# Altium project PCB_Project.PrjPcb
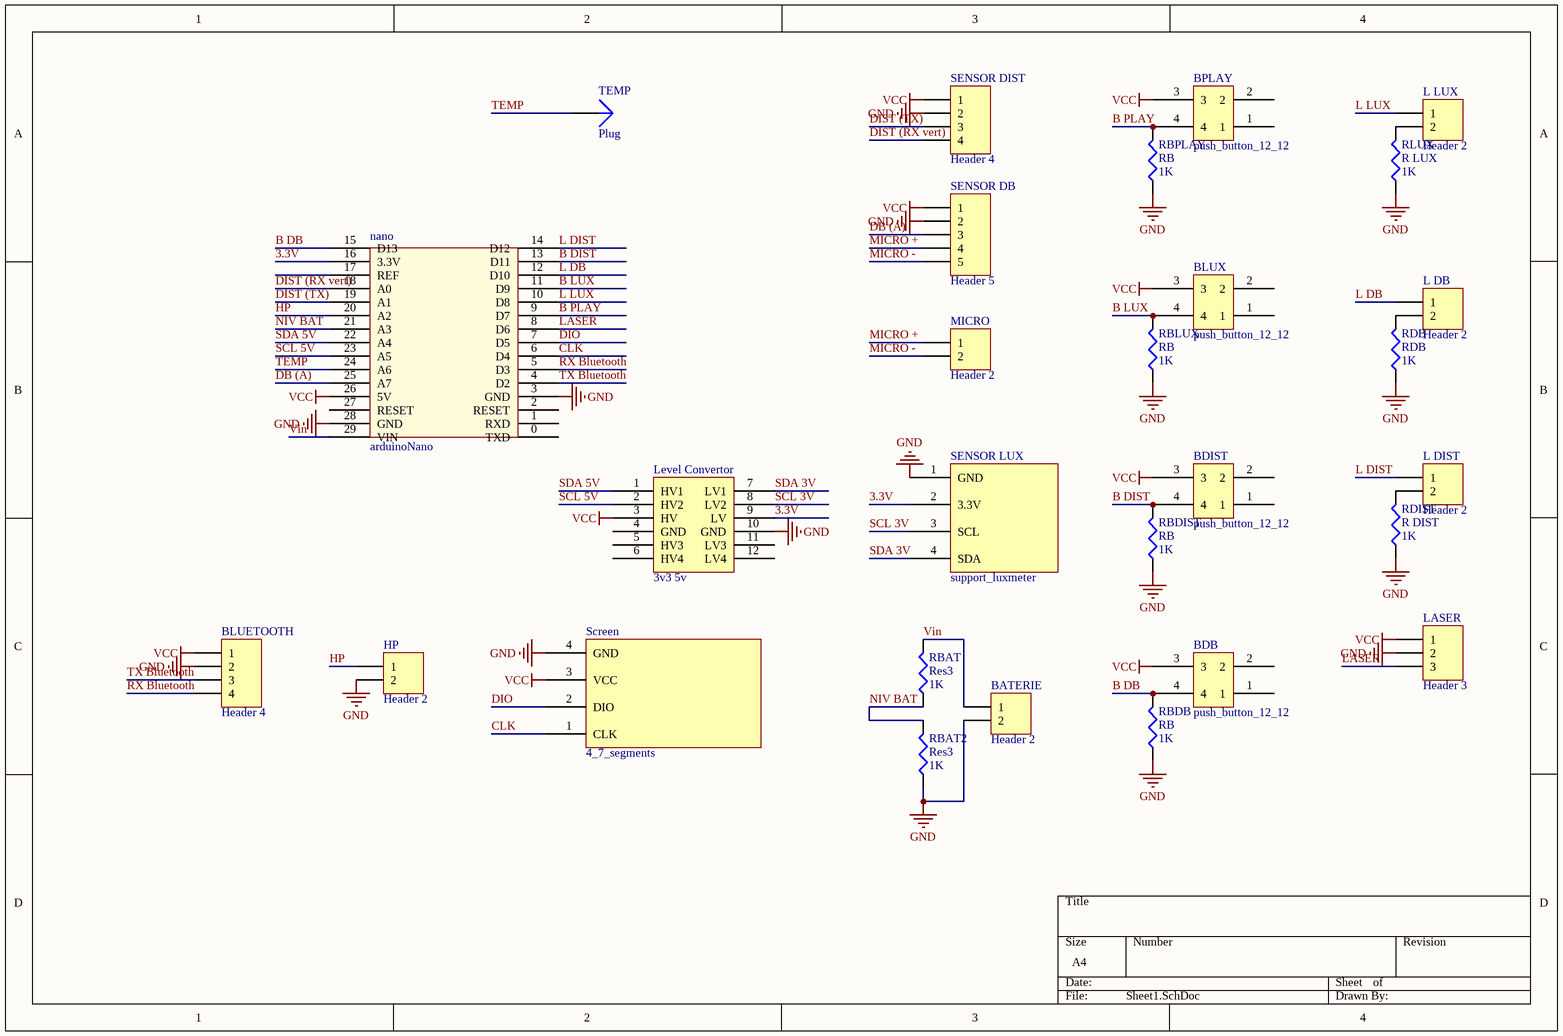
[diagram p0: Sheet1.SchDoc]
1 sheet, 28 parts. Net scope: global (net labels, ports and power ports of the same name join across sheets).
Board file: PCB1.PcbDoc

## Sheet Sheet1.SchDoc
size A4

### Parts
BATERIE  Header 2  [HDR1X2]
BDB  push_button_12_12  [push_button_12_12]
BDIST  push_button_12_12  [push_button_12_12]
BLUETOOTH  Header 4  [HDR1X4]
BLUX  push_button_12_12  [push_button_12_12]
BPLAY  push_button_12_12  [push_button_12_12]
HP  Header 2  [HDR1X2]
L_DB  Header 2  [HDR1X2]
L_DIST  Header 2  [HDR1X2]
L_LUX  Header 2  [HDR1X2]
LASER  Header 3  [HDR1X3]
Level_Convertor  3v3 5v  [level_convertor]
MICRO  Header 2  [HDR1X2]
nano  arduinoNano  [Arduino nano]
RBAT  Res3  value 1K  [C1206]
RBAT2  Res3  value 1K  [C1206]
RBDB  RB  value 1K  [C1206]
RBDIST  RB  value 1K  [C1206]
RBLUX  RB  value 1K  [C1206]
RBPLAY  RB  value 1K  [C1206]
RDB  RDB  value 1K  [C1206]
RDIST  R DIST  value 1K  [C1206]
RLUX  R LUX  value 1K  [C1206]
Screen  4_7_segments  [4_7_segment]
SENSOR_DB  Header 5  [HDR1X5]
SENSOR_DIST  Header 4  [HDR1X4]
SENSOR_LUX  support_luxmeter  [support_luxmeter]
TEMP  Plug  [PIN1]

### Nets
GND: BATERIE.2 BLUETOOTH.2 HP.2 LASER.2 Level_Convertor.10(GND) nano.3(GND) nano.28(GND) RBAT2.1 RBDB.1 RBDIST.1 RBLUX.1 RBPLAY.1 RDB.1 RDIST.1 RLUX.1 Screen.4(GND) SENSOR_DB.2 SENSOR_DIST.2 SENSOR_LUX.1(GND)
VCC: BDB.3 BDIST.3 BLUETOOTH.1 BLUX.3 BPLAY.3 LASER.1 Level_Convertor.3(HV) nano.26(5V) Screen.3(VCC) SENSOR_DB.1 SENSOR_DIST.1
3.3V: Level_Convertor.9(LV) nano.16(3.3V) SENSOR_LUX.2(3.3V)
B DB: BDB.4 nano.15(D13) RBDB.2
B DIST: BDIST.4 nano.13(D11) RBDIST.2
B LUX: BLUX.4 nano.11(D9) RBLUX.2
B PLAY: BPLAY.4 nano.9(D7) RBPLAY.2
CLK: nano.6(D4) Screen.1(CLK)
DB (A): nano.25(A7) SENSOR_DB.3
DIO: nano.7(D5) Screen.2(DIO)
DIST (RX vert): nano.18(A0) SENSOR_DIST.4
DIST (TX): nano.19(A1) SENSOR_DIST.3
HP: HP.1 nano.20(A2)
L DB: L_DB.1 nano.12(D10)
L DIST: L_DIST.1 nano.14(D12)
L LUX: L_LUX.1 nano.10(D8)
LASER: LASER.3 nano.8(D6)
MICRO +: MICRO.1 SENSOR_DB.4
MICRO -: MICRO.2 SENSOR_DB.5
NIV BAT: nano.21(A3) RBAT.1 RBAT2.2
RX Bluetooth: BLUETOOTH.4 nano.5(D3)
SCL 3V: Level_Convertor.8(LV2) SENSOR_LUX.3(SCL)
SCL 5V: Level_Convertor.2(HV2) nano.23(A5)
SDA 3V: Level_Convertor.7(LV1) SENSOR_LUX.4(SDA)
SDA 5V: Level_Convertor.1(HV1) nano.22(A4)
TEMP: nano.24(A6) TEMP.1
TX Bluetooth: BLUETOOTH.3 nano.4(D2)
Vin: BATERIE.1 nano.29(VIN) RBAT.2
NetL_DB_2: L_DB.2 RDB.2
NetL_DIST_2: L_DIST.2 RDIST.2
NetL_LUX_2: L_LUX.2 RLUX.2

Not connected (* = marked no-connect by the designer): BDB 1 2; BDIST 1 2; BLUX 1 2; BPLAY 1 2; Level_Convertor 4(GND) 5(HV3) 6(HV4) 11(LV3) 12(LV4); nano 0(TXD) 1(RXD) 2(RESET) 17(REF) 27(RESET)

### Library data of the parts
BATERIE HP L_DB L_DIST L_LUX MICRO = Header 2: Header, 2-Pin
BLUETOOTH SENSOR_DIST = Header 4: Header, 4-Pin
LASER = Header 3: Header, 3-Pin
Level_Convertor = Level_convertor
RBAT RBAT2 RBDB RBDIST RBLUX RBPLAY RDB RDIST RLUX = Res3: Resistor
SENSOR_DB = Header 5: Header, 5-Pin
